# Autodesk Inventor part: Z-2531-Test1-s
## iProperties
Created: 2009-12
Part Number: Z-2531-Test1-s
Material: VA 1.4301 III c
Document SubType Name: Blech
Designer: Strathkötter
Density: 8.08 g/cm^3
Author: Strathkötter
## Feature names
1. Abgeleiteter Körper1 [Tagging]
